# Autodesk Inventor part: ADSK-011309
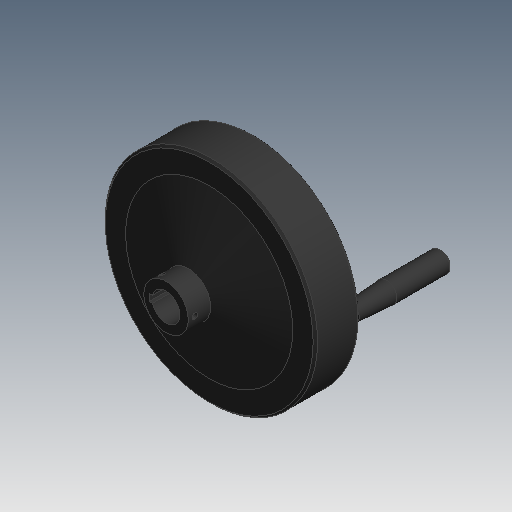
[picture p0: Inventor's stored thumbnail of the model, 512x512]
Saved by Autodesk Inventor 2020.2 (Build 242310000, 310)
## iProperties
Created: 1999-11
Part Number: ADSK-011309
Description: HANDWHEEL,6.0 DIA, 0.75  BORE,W/FOLDING HANDLE
Document SubType Name: Modeling
Designer: mpflueger
Material: Générique
Density: 1 g/cm^3
Appearance: Rubber-Black
Mass: 390.738 g
Surface Area: 636.563 cm^2
Volume: 390.738 cm^3
Control State: 0
Master: False
Checked Out: False
Shininess: 0.0
Length Units: 11269
Angle Units: 11279
Time Units: 11290
Mass Units: 11283
Length Display Precision: 3
Angle Display Precision: 2
Compacted: True
Dimensions: 152,4x128x153,5 mm
Mass: 0,391 kg
DocNumber: ADSK-011309.ipt
Folder: 01 - Themengebiete\Simplification\01 - Packaging machine\
VDS_Category: 3D Komponenten
VLT_Material: Generic
Density: 0.0
Volumn: 0.0
Area: 0.0
PropertySet Name: Model Information
Author: mpflueger
Revision Number: -
Title: handwheel
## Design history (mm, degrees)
workaxis "Work Axis2"
workpoint "Work Point1"
workpoint "Work Point2"
workplane "Work Plane8"
node "Revolution2" dims "d92" = 90 deg
workaxis "Work Axis3"
node "Revolution4" dims "d95" = 90 deg
sketch "Sketch21"
  geometry: L1 (-9.682, 2.5)-(-12, 2.5); L2 (-12, -2.5)-(-9.682, -2.5); L3 (-12, 2.5)-(-12, -2.5); C1 r 16.002 at (0, 0) reference; A1 r 10 centre (0, 0) between (-9.682, -2.5) and (-9.682, 2.5); 1 further point
  constraints: 6 end point, 2 point on circle, 1 centre point, 1 concentric, 1 horizontal, 1 horizontal alignment, 1 midpoint, 1 parallel, 1 perpendicular
  dimensions: "d55" = 20 diameter of A1; "d64" = 12 distance from line of A1.centre L3; "d97" = 5 distance of L1.end L2.start
node "Extrusion7" dims "d65" = 39.624, "d66" = 0
workplane "Work Plane5"
node "Hole2" dims "d68" = 4.134, "d69" = 4, "d70" = 2, "d71" = 60 deg, "d72" = 8, "d73" = 118 deg, "d98" = 10
workaxis "Work Axis1"
workplane "Work Plane6"
workplane "Work Plane7"
node "Hole3" dims "d76" = 4.134, "d77" = 4, "d78" = 2, "d79" = 60 deg, "d80" = 8, "d81" = 118 deg, "d99" = 10
node "Revolution1" dims "d89" = 90 deg
workplane "Work Plane3"
node "Extrusion5" dims "d33" = 12.7, "d34" = 0
workplane "Work Plane4"
node "Extrusion6" dims "d45" = 39.624, "d46" = 0
node "Fillet1" dims "d52" = 1.5875
node "Chamfer1" dims "d53" = 1.5875, "d54" = 1.5875, "d96" = 45 deg
node "Solide1"
  node "Extrusion1" dims "d1" = 32.004, "d2" = 0
  node "Extrusion2" dims "d4" = 16, "d5" = 0
workplane "Work Plane1"
node "Corps solides"
node "Corps surfaciques"
sketch "Sketch4"
  geometry: C1 r 16.002 at (0, 0) reference; C2 r 20 at (0, 0)
  constraints: 1 centre point, 1 coincident
sketch "Sketch19"
  geometry: C1 r 7.493 at (0, 0) reference; C2 r 7.493 at (0, 0)
  constraints: 1 centre point, 1 coincident
sketch "Sketch1"
  geometry: C1 r 76.2 at (0, 0)
  constraints: 1 centre point
  dimensions: "d0" = 152.4 diameter of C1
sketch "Sketch2"
  geometry: C1 r 16.002 at (0, 0)
  constraints: 1 centre point
  dimensions: "d82" = 32.004 diameter of C1
sketch "Sketch15"
  geometry: C1 r 63.5 at (0, 0); C2 r 76.2 at (0, 0) reference
  constraints: 1 centre point, 1 concentric
sketch "Sketch18"
  geometry: L1 (63.5, 0)-(76.2, 0); L2 (63.5, 0)-(76.2, 0); C1 r 76.2 at (0, 0) reference; C2 r 63.5 at (0, 0) reference; C3 r 7.493 at (69.85, 0)
  constraints: 4 end point, 1 centre point, 1 collinear, 1 horizontal, 1 midpoint
  dimensions: "d44" = 14.986 diameter of C3
sketch "Sketch22"
  geometry: L1 (-16.002, 0)-(16.002, 0); L2 (-2.5, 30.988)-(2.5, 30.988) reference; 2 further points; 1 other entity
  constraints: 2 end point, 1 other
  dimensions: "d83" = 4.7625 distance from line of point (-0.119, 26.226) L2; "d84" = 2.38125 dimension on point (-0.119, 26.226)
sketch "Sketch23"
  geometry: L1 (-16.002, 0)-(16.002, 0) reference; 1 further point
  dimensions: "d75" = 4.7625 distance from line of point (0, -4.763) L1; "d85" = 16.002 horizontal distance of L1.end point (0, -4.763) (= 0.5 x d82)
sketch "Sketch24"
  geometry: L1 (-16.002, 30.988)-(-16.002, 14.988) reference; L2 (-74.612, 0)-(74.612, 0) reference; L3 (-16.002, 14.988)-(-59.995, 0); L4 (-16.002, 14.988)-(0, 14.988); L5 (0, 14.988)-(0, 0); L6 (0, 0)-(-59.995, 0)
  constraints: 8 end point, 2 perpendicular, 1 parallel, 1 point on line
  dimensions: "d88" = 59.9948 distance of L5.end L3.end
sketch "Sketch25"
  geometry: L1 (7.493, 1.587)-(7.493, 39.624) reference; L2 (74.612, 65.024)-(-74.612, 65.024) reference; L3 (7.493, 39.624)-(5.905, 65.024); L4 (5.905, 65.024)-(0, 65.024); L5 (0, 65.024)-(0, 39.624); L6 (0, 39.624)-(7.493, 39.624)
  constraints: 8 end point, 2 perpendicular, 1 collinear, 1 point on line
  dimensions: "d91" = 5.9055 distance of L3.end L4.end
sketch "Sketch26"
  geometry: L1 (-74.612, 0)-(74.612, 0) reference; L2 (-76.2, -1.587)-(-76.2, -30.417) reference; L3 (-16.002, 30.988)-(-16.002, 14.988) reference; L4 (16.002, 30.988)-(16.002, 14.988) reference; L5 (76.2, -1.587)-(76.2, -30.417) reference; L6 (63.5, -30.417)-(63.5, -19.304) reference; L7 (10, -19.304)-(-10, -19.304) reference; L8 (10, 30.988)-(10, 14.988) reference; L9 (10, 14.988)-(-10, 14.988) reference; L10 (10, 0)-(10, 14.988); L11 (0, 48.666)-(0, -75.082) reference; L12 (10, 14.988)-(0, 14.988); L13 (0, 14.988)-(0, -19.304); L14 (0, -19.304)-(63.5, -19.304); L15 (10, 0)-(22.225, 0); L16 (22.225, 0)-(63.5, -19.304); L17 (22.225, 0)-(10, 0); L18 (10, 14.988)-(0, 14.988); L19 (0, 14.988)-(0, -19.304); 4 further points
  constraints: 18 end point, 3 point on line, 2 collinear, 2 midpoint, 2 perpendicular, 1 parallel
  dimensions: "d94" = 22.225 distance from line of L15.end L13
other parameters: "d3" = 30.988, "d15" = -128.016, "d36" = 6.35, "d74" = 60 deg, "d90" = 90 deg
